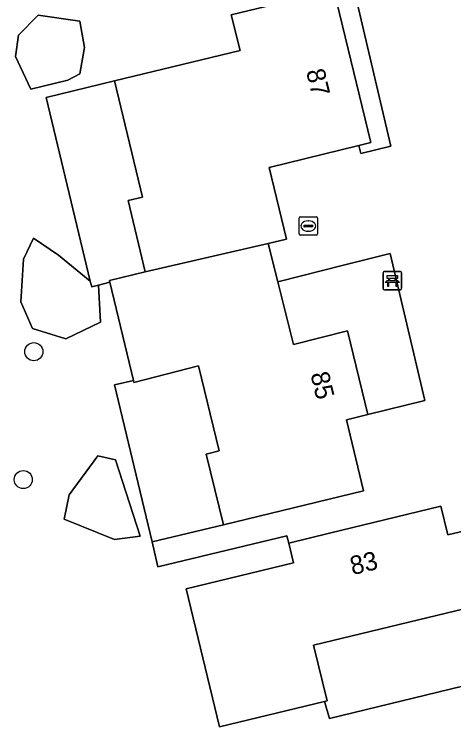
# Model space of a CAD drawing. Extents: x 156661 to 157576, y 383570 to 384425.
# Drawn here: x 156926.82 to 156950.61, y 384049.95 to 384088.47 of the extents above; entities that cross this region are included whole.
import ezdxf

# ---------------------------------------------------------------- set-up
doc = ezdxf.new("R2010")
doc.units = 0
for name, color, linetype in [('IMGEO_Bank', 7, 'Continuous'), ('IMGEO_Boom', 7, 'Continuous'), ('IMGEO_Erf', 7, 'Continuous'), ('IMGEO_Groenvoorziening', 7, 'Continuous'), ('IMGEO_Kolk', 7, 'Continuous'), ('IMGEO_Pand', 7, 'Continuous'), ('IMGEO_Pand_nummerreeks', 7, 'Continuous'), ('IMGEO_Rijbaan_lokaal_open', 7, 'Continuous')]:
    doc.layers.add(name, color=color, linetype=linetype)

msp = doc.modelspace()

# ---------------------------------------------------------------- linework, layer by layer
at = {"layer": 'IMGEO_Bank'}
for p, q in [((156946.784, 384073.642), (156946.784, 384074.483)), ((156946.784, 384074.483), (156946.784, 384073.642)), ((156946.859, 384074.567), (156947.7, 384074.567)), ((156947.7, 384074.567), (156946.859, 384074.567)), ((156947.784, 384074.492), (156947.784, 384073.651)), ((156947.784, 384073.651), (156947.784, 384074.492)), ((156947.481, 384073.965), (156947.088, 384073.965)), ((156947.093, 384074.073), (156947.093, 384074.179)), ((156947.137, 384074.179), (156947.137, 384074.073)), ((156947.425, 384074.185), (156947.143, 384074.185)), ((156947.143, 384074.067), (156947.425, 384074.067)), ((156947.431, 384074.073), (156947.431, 384074.179)), ((156947.475, 384074.179), (156947.475, 384074.073)), ((156947.709, 384073.567), (156946.868, 384073.567)), ((156946.868, 384073.567), (156947.709, 384073.567))]:
    msp.add_line(p, q, dxfattribs=at)
for points in [[(156947.087, 384074.185), (156947.001, 384074.185), (156947.001, 384074.346), (156947.564, 384074.346), (156947.564, 384074.185), (156947.481, 384074.185)], [(156947.031, 384073.965), (156946.889, 384073.965), (156947.001, 384074.067), (156947.087, 384074.067)], [(156947.081, 384073.958), (156947.081, 384073.751), (156947.038, 384073.751), (156947.038, 384073.958)], [(156947.481, 384074.067), (156947.564, 384074.067), (156947.676, 384073.965), (156947.537, 384073.965)], [(156947.531, 384073.958), (156947.531, 384073.751), (156947.487, 384073.751), (156947.487, 384073.958)]]:
    msp.add_lwpolyline(points, dxfattribs=at)
for centre, radius, start, end in [((156946.862, 384074.489), 0.0779, 92.4484, 184.2845), ((156946.862, 384074.489), 0.0779, 92.4484, 184.2845), ((156947.706, 384074.489), 0.0779, 2.4484, 94.2845), ((156947.706, 384074.489), 0.0779, 2.4484, 94.2845), ((156947.031, 384073.958), 0.00671, 2.8957, 87.1043), ((156947.088, 384073.958), 0.00671, 92.8957, 177.1043), ((156947.086, 384074.178), 0.00671, 2.8957, 87.1043), ((156947.086, 384074.074), 0.00671, 272.8957, 357.1043), ((156947.143, 384074.178), 0.00671, 92.8957, 177.1043), ((156947.143, 384074.074), 0.00671, 182.8957, 267.1043), ((156947.425, 384074.178), 0.00671, 2.8957, 87.1043), ((156947.425, 384074.074), 0.00671, 272.8957, 357.1043), ((156947.482, 384074.178), 0.00671, 92.8957, 177.1043), ((156947.482, 384074.074), 0.00671, 182.8957, 267.1043), ((156947.48, 384073.958), 0.00671, 2.8957, 87.1043), ((156947.537, 384073.958), 0.00671, 92.8957, 177.1043), ((156946.862, 384073.645), 0.0779, 182.4484, 274.2845), ((156946.862, 384073.645), 0.0779, 182.4484, 274.2845), ((156947.706, 384073.645), 0.0779, 272.4484, 4.2845), ((156947.706, 384073.645), 0.0779, 272.4484, 4.2845)]:
    msp.add_arc(centre, radius, start, end, dxfattribs=at)
at = {"layer": 'IMGEO_Boom'}
for centre in [(156927.885, 384070.223), (156927.314, 384063.308)]:
    msp.add_circle(centre, 0.489, dxfattribs=at)
at = {"layer": 'IMGEO_Erf'}
for points in [[(156932.249, 384084.864), (156928.555, 384083.965), (156930.939, 384074.036), (156931.014, 384073.724), (156931.381, 384073.823), (156931.993, 384073.988), (156931.973, 384074.071), (156933.906, 384074.537), (156932.99, 384078.392), (156933.768, 384078.586)], [(156936.794, 384069.462), (156933.304, 384068.552), (156933.275, 384068.671), (156932.258, 384068.433), (156934.279, 384059.95), (156938.142, 384060.86), (156937.21, 384064.69), (156937.909, 384064.859)], [(156951.245, 384056.344), (156943.017, 384054.348), (156943.754, 384051.343), (156943.607, 384051.308), (156943.875, 384050.383), (156952.343, 384052.441), (156952.269, 384052.774), (156952.113, 384052.736)]]:
    msp.add_lwpolyline(points, close=True, dxfattribs=at)
at = {"layer": 'IMGEO_Groenvoorziening'}
msp.add_lwpolyline([(156952.343, 384052.441), (156943.875, 384050.383), (156943.607, 384051.308), (156937.932, 384049.945), (156936.129, 384057.408), (156941.935, 384058.813), (156941.675, 384059.88), (156941.578, 384060.276), (156934.593, 384058.597), (156934.279, 384059.95), (156932.258, 384068.433), (156933.275, 384068.671), (156931.993, 384073.988), (156931.381, 384073.823), (156931.493, 384071.828), (156929.611, 384070.922), (156927.808, 384071.475), (156927.188, 384072.915), (156927.327, 384075.229), (156927.86, 384076.367), (156929.215, 384075.434), (156930.939, 384074.036), (156928.555, 384083.965), (156932.249, 384084.864), (156939.043, 384086.504), (156938.568, 384088.437), (156944.115, 384089.783), (156946.117, 384081.533), (156945.461, 384081.373), (156945.581, 384080.944), (156947.199, 384081.344), (156943.484, 384097.16)], dxfattribs=at)
for points in [[(156930.372, 384085.253), (156929.73, 384084.91), (156927.724, 384084.412), (156926.896, 384086.189), (156927.054, 384087.341), (156928.116, 384088.422), (156930.38, 384088.099), (156930.622, 384086.679)], [(156930.372, 384085.253), (156930.622, 384086.679), (156930.38, 384088.099), (156928.116, 384088.422), (156927.054, 384087.341), (156926.896, 384086.189), (156927.724, 384084.412), (156929.73, 384084.91)], [(156931.381, 384073.823), (156931.014, 384073.724), (156930.939, 384074.036), (156929.215, 384075.434), (156927.86, 384076.367), (156927.327, 384075.229), (156927.188, 384072.915), (156927.808, 384071.475), (156929.611, 384070.922), (156931.493, 384071.828)], [(156941.086, 384074.007), (156941.936, 384070.617), (156944.852, 384071.347), (156945.951, 384066.823), (156949.042, 384067.577), (156947.16, 384075.531), (156944.634, 384074.898)], [(156932.296, 384064.374), (156933.639, 384060.251), (156932.242, 384060.074), (156929.523, 384061.161), (156929.804, 384062.481), (156931.353, 384064.601)], [(156932.296, 384064.374), (156931.353, 384064.601), (156929.804, 384062.481), (156929.523, 384061.161), (156932.242, 384060.074), (156933.639, 384060.251)]]:
    msp.add_lwpolyline(points, close=True, dxfattribs=at)
at = {"layer": 'IMGEO_Kolk'}
for p, q in [((156942.232, 384076.592), (156942.232, 384077.444)), ((156942.307, 384077.518), (156943.159, 384077.518)), ((156943.233, 384077.444), (156943.233, 384076.592)), ((156942.491, 384077.012), (156942.491, 384077.024)), ((156942.929, 384076.975), (156942.531, 384076.975)), ((156942.534, 384077.061), (156942.932, 384077.061)), ((156942.72, 384077.298), (156942.745, 384077.298)), ((156942.975, 384077.024), (156942.975, 384077.012)), ((156942.743, 384076.738), (156942.718, 384076.738)), ((156943.159, 384076.518), (156942.307, 384076.518))]:
    msp.add_line(p, q, dxfattribs=at)
for points in [[(156942.232, 384076.592), (156942.232, 384077.444)], [(156942.307, 384077.518), (156943.159, 384077.518)], [(156943.233, 384077.444), (156943.233, 384076.592)], [(156943.159, 384076.518), (156942.307, 384076.518)]]:
    msp.add_lwpolyline(points, dxfattribs=at)
for centre, radius, start, end in [((156942.309, 384077.442), 0.0765, 91.552, 178.448), ((156942.309, 384077.442), 0.0765, 91.552, 178.448), ((156943.157, 384077.442), 0.0765, 1.552, 88.448), ((156943.157, 384077.442), 0.0765, 1.552, 88.448), ((156942.531, 384077.021), 0.0403, 85.8775, 175.7526), ((156942.528, 384077.011), 0.0366, 178.938, 274.7102), ((156942.932, 384077.018), 0.043, 264.8664, 352.4533), ((156942.936, 384077.023), 0.0386, 1.7309, 96.639), ((156942.309, 384076.594), 0.0765, 181.552, 268.448), ((156942.309, 384076.594), 0.0765, 181.552, 268.448), ((156943.157, 384076.594), 0.0765, 271.552, 358.448), ((156943.157, 384076.594), 0.0765, 271.552, 358.448)]:
    msp.add_arc(centre, radius, start, end, dxfattribs=at)
for centre, major_axis, ratio, start_param, end_param in [((156942.719, 384077.018), (-0.387, 0.002), 0.722429, 4.712389, 7.853982), ((156942.744, 384077.018), (-0.39, 0.002), 0.717154, 1.570796, 4.712389)]:
    msp.add_ellipse(centre, major_axis=major_axis, ratio=ratio, start_param=start_param, end_param=end_param, dxfattribs=at)
at = {"layer": 'IMGEO_Pand'}
for points in [[(156944.115, 384089.783), (156938.568, 384088.437), (156939.043, 384086.504), (156932.249, 384084.864), (156933.768, 384078.586), (156932.99, 384078.392), (156933.906, 384074.537), (156940.57, 384076.066), (156941.558, 384076.308), (156940.609, 384080.187), (156945.461, 384081.373), (156946.117, 384081.533)], [(156944.852, 384071.347), (156941.936, 384070.617), (156941.086, 384074.007), (156940.57, 384076.066), (156933.906, 384074.537), (156931.973, 384074.071), (156931.993, 384073.988), (156933.275, 384068.671), (156933.304, 384068.552), (156936.794, 384069.462), (156937.909, 384064.859), (156937.21, 384064.69), (156938.142, 384060.86), (156945.72, 384062.703), (156944.796, 384066.546), (156945.951, 384066.823)], [(156955.834, 384061.641), (156950.278, 384060.318), (156949.912, 384061.866), (156943.889, 384060.413), (156941.675, 384059.88), (156941.935, 384058.813), (156936.129, 384057.408), (156937.932, 384049.945), (156943.607, 384051.308), (156943.754, 384051.343), (156943.017, 384054.348), (156951.245, 384056.344), (156952.113, 384052.736), (156952.269, 384052.774), (156957.651, 384054.07)]]:
    msp.add_lwpolyline(points, close=True, dxfattribs=at)
at = {"layer": 'IMGEO_Rijbaan_lokaal_open'}
msp.add_lwpolyline([(156943.484, 384097.16), (156947.199, 384081.344), (156945.581, 384080.944), (156945.461, 384081.373), (156940.609, 384080.187), (156941.558, 384076.308), (156940.57, 384076.066), (156941.086, 384074.007), (156944.634, 384074.898), (156947.16, 384075.531), (156949.042, 384067.577), (156945.951, 384066.823), (156944.796, 384066.546), (156945.72, 384062.703), (156938.142, 384060.86), (156934.279, 384059.95), (156934.593, 384058.597), (156941.578, 384060.276), (156941.675, 384059.88), (156943.889, 384060.413), (156949.912, 384061.866), (156950.278, 384060.318), (156955.834, 384061.641)], dxfattribs=at)

# ---------------------------------------------------------------- texts
at = {"layer": 'IMGEO_Pand_nummerreeks'}
for s, rotation, p in [('87', 283.6419, (156942.608, 384085.394)), ('85', 283.6534, (156942.846, 384069.014)), ('83', 13.5619, (156945.127, 384058.14))]:
    msp.add_text(s, height=1, rotation=rotation, dxfattribs=at).set_placement(p)

doc.saveas('drawing.dxf')
